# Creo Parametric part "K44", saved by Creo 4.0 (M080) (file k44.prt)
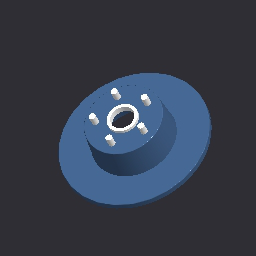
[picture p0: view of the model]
Units: Inch lbm Second (Pro/E Default); INCH, POUND, SECS

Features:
  1. datum plane "DTM3"
  2. datum plane "DTM4"
  3. datum plane "DTM5"
  4. protrusion
  5. hole
  6. cut
  7. protrusion
  8. pattern
  9. datum plane "DTM7"
  10. datum plane "DTM8"
  11. protrusion
  12. protrusion
  13. protrusion
  14. protrusion
  15. protrusion
  16. round

Layers: BASE_DAT, BLANK

Surfaces: 10 plane, 10 cylinder, 6 torus, 4 cone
